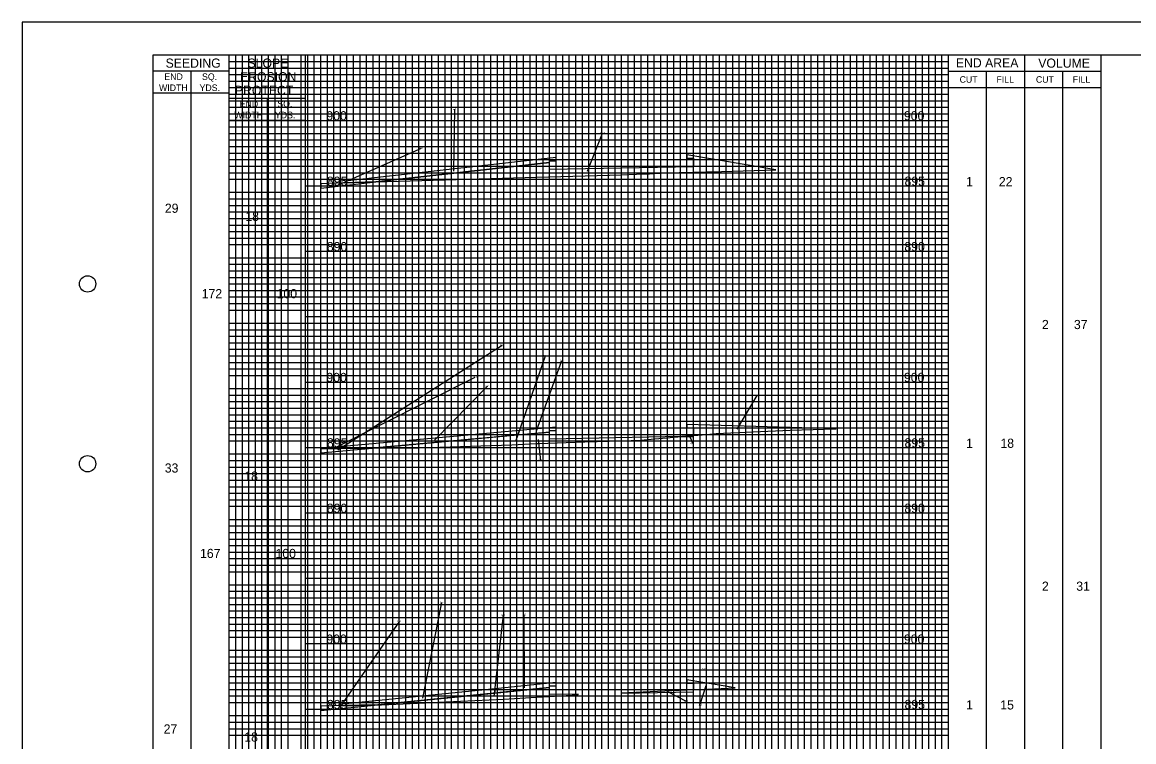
# Model space of a CAD drawing. Extents: x -73 to 160, y -2 to 1877.
# Drawn here: x -10 to 75, y 52.5 to 107.5 of the extents above; entities that cross this region are included whole.
import ezdxf

# ---------------------------------------------------------------- set-up
doc = ezdxf.new("R2010")
doc.units = 0
for name, color, linetype in [('DR_P_Flood_Boundary', 7, 'Continuous'), ('GK_Cells', 7, 'Continuous'), ('RD_X_Fence', 7, 'Continuous'), ('TX_X_5', 7, 'Continuous'), ('UT_P_Water_Cells', 7, 'Continuous'), ('XS_P_Pavt_Surface', 7, 'Continuous'), ('XS_X_Ground_Line', 7, 'Continuous')]:
    doc.layers.add(name, color=color, linetype=linetype)

msp = doc.modelspace()

# ---------------------------------------------------------------- linework, layer by layer
at = {"layer": 'DR_P_Flood_Boundary'}
for p, q in [((15.832, 0), (15.832, 105)), ((20.832, 0), (20.832, 105)), ((25.832, 0), (25.832, 105)), ((30.832, 0), (30.832, 105)), ((35.832, 0), (35.832, 105)), ((40.832, 0), (40.832, 105)), ((45.832, 0), (45.832, 105)), ((50.832, 0), (50.832, 105)), ((55.832, 0), (55.832, 105)), ((5.832, 100), (60.832, 100)), ((11.665, 95), (60.832, 95)), ((11.665, 90), (60.832, 90)), ((11.665, 85), (60.832, 85)), ((11.665, 80), (60.832, 80)), ((11.665, 75), (60.832, 75)), ((11.665, 70), (60.832, 70)), ((11.665, 65), (60.832, 65)), ((11.665, 60), (60.832, 60)), ((11.665, 55), (60.832, 55))]:
    msp.add_line(p, q, dxfattribs=at)
at = {"layer": 'GK_Cells'}
msp.add_lwpolyline([(0, 105), (157.5, 105), (157.5, 0), (0, 0)], close=True, dxfattribs=at)
for centre in [(-5, 87.5), (-5, 73.75)]:
    msp.add_circle(centre, 0.625, dxfattribs=at)
at = {"layer": 'RD_X_Fence'}
for p, q in [((23.016, 96.129), (23.081, 100.856)), ((33.227, 96.12), (34.386, 99.017)), ((14.249, 95.09), (20.533, 97.869)), ((30.832, 97.162), (14.91, 95.382)), ((30.332, 96.902), (30.832, 96.912)), ((30.332, 96.776), (30.332, 96.902)), ((30.832, 97.058), (30.832, 97.162)), ((30.832, 96.912), (30.832, 97.058)), ((47.628, 96.229), (40.832, 97.362)), ((40.832, 97.112), (41.332, 97.122)), ((41.332, 97.122), (41.332, 96.455)), ((30.332, 96.776), (17.034, 95.29)), ((17.034, 95.29), (30.332, 96.776)), ((30.332, 96.235), (30.332, 96.776)), ((41.332, 96.455), (30.332, 96.235)), ((40.235, 96.02), (42.332, 96.069)), ((12.833, 94.82), (17.034, 95.29)), ((14.625, 95.219), (12.833, 95.15)), ((14.91, 95.382), (14.611, 95.25)), ((17.034, 95.29), (14.625, 95.219)), ((14.625, 95.219), (17.034, 95.29)), ((17.034, 95.29), (29.332, 95.65)), ((29.332, 95.65), (35.832, 95.841)), ((38.255, 95.926), (38.86, 95.952)), ((38.86, 95.952), (40.235, 96.02)), ((12.833, 95.15), (12.833, 94.82)), ((14.141, 74.81), (26.701, 82.806)), ((27.741, 75.48), (30.016, 81.999)), ((29.336, 76.257), (31.276, 81.639)), ((13.897, 74.966), (24.643, 80.369)), ((21.519, 75.544), (25.574, 79.685)), ((44.662, 76.391), (46.189, 78.96)), ((30.832, 76.553), (28.027, 76.297)), ((30.832, 76.449), (30.832, 76.553)), ((52.245, 76.425), (40.832, 76.753)), ((40.832, 76.503), (41.332, 76.513)), ((41.332, 76.513), (41.332, 75.909)), ((28.027, 76.297), (14.544, 75.066)), ((30.332, 76.177), (16.757, 74.938)), ((16.757, 74.938), (27.908, 75.956)), ((27.908, 75.956), (28.027, 76.297)), ((28.027, 76.297), (27.908, 75.956)), ((27.908, 75.956), (30.332, 76.177)), ((30.332, 76.293), (30.832, 76.303)), ((30.332, 76.177), (30.332, 76.293)), ((30.332, 75.626), (30.332, 76.177)), ((40.428, 75.828), (30.332, 75.626)), ((30.832, 76.303), (30.832, 76.449)), ((41.327, 75.909), (40.428, 75.828)), ((40.428, 75.828), (41.332, 75.846)), ((41.029, 75.861), (41.277, 75.294)), ((14.544, 75.066), (12.833, 74.91)), ((12.833, 74.58), (16.757, 74.938)), ((16.757, 74.938), (12.833, 74.91)), ((12.833, 74.91), (14.316, 74.921)), ((12.833, 74.91), (12.833, 74.58)), ((14.544, 75.066), (14.316, 74.921)), ((14.316, 74.921), (14.544, 75.066)), ((14.316, 74.921), (16.757, 74.938)), ((29.462, 75.605), (29.62, 74.009)), ((29.492, 75.305), (33.032, 75.416)), ((20.631, 55.846), (22.093, 63.149)), ((26.087, 55.967), (26.81, 62.171)), ((28.415, 56.625), (28.382, 62.213)), ((14.305, 55.148), (18.867, 61.716)), ((30.832, 57.03), (26.156, 56.559)), ((44.508, 56.617), (40.832, 57.23)), ((40.832, 56.98), (41.332, 56.99)), ((41.332, 56.99), (41.332, 56.475)), ((26.156, 56.559), (14.468, 55.384)), ((30.332, 56.649), (16.931, 55.302)), ((16.931, 55.302), (26.117, 56.225)), ((26.117, 56.225), (30.332, 56.649)), ((26.117, 56.225), (26.156, 56.559)), ((26.156, 56.559), (26.117, 56.225)), ((30.332, 56.77), (30.832, 56.78)), ((30.332, 56.649), (30.332, 56.77)), ((30.332, 56.103), (30.332, 56.649)), ((32.519, 56.147), (30.332, 56.103)), ((41.332, 56.475), (35.832, 56.228)), ((35.833, 56.213), (41.332, 56.323)), ((39.337, 56.334), (40.812, 55.57)), ((41.332, 56.475), (44.508, 56.617)), ((41.332, 56.323), (41.332, 56.475)), ((42.276, 56.776), (41.82, 55.342)), ((16.928, 55.329), (12.833, 55.219)), ((12.833, 54.889), (16.931, 55.302)), ((14.468, 55.384), (14.376, 55.25)), ((14.376, 55.25), (16.931, 55.302)), ((29.332, 55.906), (32.52, 56.079)), ((12.833, 55.219), (12.833, 54.889))]:
    msp.add_line(p, q, dxfattribs=at)
for points in [[(40.832, 97.362), (40.832, 97.258), (40.832, 97.112)], [(42.332, 96.069), (43.472, 96.095), (47.628, 96.229)], [(14.611, 95.25), (14.625, 95.219)], [(35.832, 95.841), (36.98, 95.881), (37.971, 95.916), (38.255, 95.926)], [(40.832, 76.753), (40.832, 76.649), (40.832, 76.503)], [(37.293, 75.549), (37.791, 75.593), (40.428, 75.828)], [(41.332, 75.846), (41.327, 75.909)], [(41.332, 75.909), (42.332, 75.998), (43.061, 76.063), (48.714, 76.326), (52.245, 76.425)], [(16.757, 74.938), (20.355, 74.964), (27.435, 75.203), (29.344, 75.3), (29.492, 75.305)], [(33.032, 75.416), (35.832, 75.503), (37.293, 75.549)], [(30.832, 56.78), (30.832, 56.925), (30.832, 57.03)], [(40.832, 57.23), (40.832, 57.125), (40.832, 56.98)], [(32.52, 56.079), (32.519, 56.147)], [(35.832, 56.228), (35.833, 56.213)], [(16.931, 55.302), (16.928, 55.329)], [(16.931, 55.302), (26.792, 55.767), (29.332, 55.906)]]:
    msp.add_lwpolyline(points, dxfattribs=at)
at = {"layer": 'TX_X_5'}
msp.add_lwpolyline([(-10, -2.5), (160, -2.5), (160, 107.5), (-10, 107.5)], close=True, dxfattribs=at)
at = {"layer": 'UT_P_Water_Cells'}
for p, q in [((6.332, 0), (6.332, 105)), ((6.832, 0), (6.832, 105)), ((7.332, 0), (7.332, 105)), ((7.832, 0), (7.832, 105)), ((8.332, 0), (8.332, 105)), ((8.832, 0), (8.832, 105)), ((9.332, 0), (9.332, 105)), ((9.832, 0), (9.832, 105)), ((10.332, 0), (10.332, 105)), ((11.332, 0), (11.332, 105)), ((11.832, 0), (11.832, 105)), ((12.332, 0), (12.332, 105)), ((12.832, 0), (12.832, 105)), ((13.332, 0), (13.332, 105)), ((13.832, 0), (13.832, 105)), ((14.332, 0), (14.332, 105)), ((14.832, 0), (14.832, 105)), ((15.332, 0), (15.332, 105)), ((16.332, 0), (16.332, 105)), ((16.832, 0), (16.832, 105)), ((17.332, 0), (17.332, 105)), ((17.832, 0), (17.832, 105)), ((18.332, 0), (18.332, 105)), ((18.832, 0), (18.832, 105)), ((19.332, 0), (19.332, 105)), ((19.832, 0), (19.832, 105)), ((20.332, 0), (20.332, 105)), ((21.332, 0), (21.332, 105)), ((21.832, 0), (21.832, 105)), ((22.332, 0), (22.332, 105)), ((22.832, 0), (22.832, 105)), ((23.332, 0), (23.332, 105)), ((23.832, 0), (23.832, 105)), ((24.332, 0), (24.332, 105)), ((24.832, 0), (24.832, 105)), ((25.332, 0), (25.332, 105)), ((26.332, 0), (26.332, 105)), ((26.832, 0), (26.832, 105)), ((27.332, 0), (27.332, 105)), ((27.832, 0), (27.832, 105)), ((28.332, 0), (28.332, 105)), ((28.832, 0), (28.832, 105)), ((29.332, 0), (29.332, 105)), ((29.832, 0), (29.832, 105)), ((30.332, 0), (30.332, 105)), ((31.332, 0), (31.332, 105)), ((31.832, 0), (31.832, 105)), ((32.332, 0), (32.332, 105)), ((32.832, 0), (32.832, 105)), ((33.332, 0), (33.332, 105)), ((33.832, 0), (33.832, 105)), ((34.332, 0), (34.332, 105)), ((34.832, 0), (34.832, 105)), ((35.332, 0), (35.332, 105)), ((36.332, 0), (36.332, 105)), ((36.832, 0), (36.832, 105)), ((37.332, 0), (37.332, 105)), ((37.832, 0), (37.832, 105)), ((38.332, 0), (38.332, 105)), ((38.832, 0), (38.832, 105)), ((39.332, 0), (39.332, 105)), ((39.832, 0), (39.832, 105)), ((40.332, 0), (40.332, 105)), ((41.332, 0), (41.332, 105)), ((41.832, 0), (41.832, 105)), ((42.332, 0), (42.332, 105)), ((42.832, 0), (42.832, 105)), ((43.332, 0), (43.332, 105)), ((43.832, 0), (43.832, 105)), ((44.332, 0), (44.332, 105)), ((44.832, 0), (44.832, 105)), ((45.332, 0), (45.332, 105)), ((46.332, 0), (46.332, 105)), ((46.832, 0), (46.832, 105)), ((47.332, 0), (47.332, 105)), ((47.832, 0), (47.832, 105)), ((48.332, 0), (48.332, 105)), ((48.832, 0), (48.832, 105)), ((49.332, 0), (49.332, 105)), ((49.832, 0), (49.832, 105)), ((50.332, 0), (50.332, 105)), ((51.332, 0), (51.332, 105)), ((51.832, 0), (51.832, 105)), ((52.332, 0), (52.332, 105)), ((52.832, 0), (52.832, 105)), ((53.332, 0), (53.332, 105)), ((53.832, 0), (53.832, 105)), ((54.332, 0), (54.332, 105)), ((54.832, 0), (54.832, 105)), ((55.332, 0), (55.332, 105)), ((56.332, 0), (56.332, 105)), ((56.832, 0), (56.832, 105)), ((57.332, 0), (57.332, 105)), ((57.832, 0), (57.832, 105)), ((58.332, 0), (58.332, 105)), ((58.832, 0), (58.832, 105)), ((59.332, 0), (59.332, 105)), ((59.832, 0), (59.832, 105)), ((60.332, 0), (60.332, 105)), ((5.832, 104.5), (60.832, 104.5)), ((5.832, 104), (60.832, 104)), ((5.832, 103.5), (60.832, 103.5)), ((5.832, 103), (60.832, 103)), ((5.832, 102.5), (60.832, 102.5)), ((5.832, 102), (60.832, 102)), ((5.832, 101.5), (60.832, 101.5)), ((5.832, 101), (60.832, 101)), ((5.832, 100.5), (60.832, 100.5)), ((5.832, 99.5), (60.832, 99.5)), ((5.832, 99), (60.832, 99)), ((5.832, 98.5), (60.832, 98.5)), ((5.832, 98), (60.832, 98)), ((5.832, 97.5), (60.832, 97.5)), ((5.832, 97), (60.832, 97)), ((5.832, 96.5), (60.832, 96.5)), ((5.832, 96), (60.832, 96)), ((5.832, 95.5), (60.832, 95.5)), ((5.832, 94.5), (60.832, 94.5)), ((5.832, 94), (60.832, 94)), ((5.832, 93.5), (60.832, 93.5)), ((5.832, 93), (60.832, 93)), ((5.832, 92.5), (60.832, 92.5)), ((5.832, 92), (60.832, 92)), ((5.832, 91.5), (60.832, 91.5)), ((5.832, 91), (60.832, 91)), ((5.832, 90.5), (60.832, 90.5)), ((5.832, 89.5), (60.832, 89.5)), ((5.832, 89), (60.832, 89)), ((5.832, 88.5), (60.832, 88.5)), ((5.832, 88), (60.832, 88)), ((5.832, 87.5), (60.832, 87.5)), ((5.832, 87), (60.832, 87)), ((5.832, 86.5), (60.832, 86.5)), ((5.832, 86), (60.832, 86)), ((5.832, 85.5), (60.832, 85.5)), ((5.832, 84.5), (60.832, 84.5)), ((5.832, 84), (60.832, 84)), ((5.832, 83.5), (60.832, 83.5)), ((5.832, 83), (60.832, 83)), ((5.832, 82.5), (60.832, 82.5)), ((5.832, 82), (60.832, 82)), ((5.832, 81.5), (60.832, 81.5)), ((5.832, 81), (60.832, 81)), ((5.832, 80.5), (60.832, 80.5)), ((5.832, 79.5), (60.832, 79.5)), ((5.832, 79), (60.832, 79)), ((5.832, 78.5), (60.832, 78.5)), ((5.832, 78), (60.832, 78)), ((5.832, 77.5), (60.832, 77.5)), ((5.832, 77), (60.832, 77)), ((5.832, 76.5), (60.832, 76.5)), ((5.832, 76), (60.832, 76)), ((5.832, 75.5), (60.832, 75.5)), ((5.832, 74.5), (60.832, 74.5)), ((5.832, 74), (60.832, 74)), ((5.832, 73.5), (60.832, 73.5)), ((5.832, 73), (60.832, 73)), ((5.832, 72.5), (60.832, 72.5)), ((5.832, 72), (60.832, 72)), ((5.832, 71.5), (60.832, 71.5)), ((5.832, 71), (60.832, 71)), ((5.832, 70.5), (60.832, 70.5)), ((5.832, 69.5), (60.832, 69.5)), ((5.832, 69), (60.832, 69)), ((5.832, 68.5), (60.832, 68.5)), ((5.832, 68), (60.832, 68)), ((5.832, 67.5), (60.832, 67.5)), ((5.832, 67), (60.832, 67)), ((5.832, 66.5), (60.832, 66.5)), ((5.832, 66), (60.832, 66)), ((5.832, 65.5), (60.832, 65.5)), ((5.832, 64.5), (60.832, 64.5)), ((5.832, 64), (60.832, 64)), ((5.832, 63.5), (60.832, 63.5)), ((5.832, 63), (60.832, 63)), ((5.832, 62.5), (60.832, 62.5)), ((5.832, 62), (60.832, 62)), ((5.832, 61.5), (60.832, 61.5)), ((5.832, 61), (60.832, 61)), ((5.832, 60.5), (60.832, 60.5)), ((5.832, 59.5), (60.832, 59.5)), ((5.832, 59), (60.832, 59)), ((5.832, 58.5), (60.832, 58.5)), ((5.832, 58), (60.832, 58)), ((5.832, 57.5), (60.832, 57.5)), ((5.832, 57), (60.832, 57)), ((5.832, 56.5), (60.832, 56.5)), ((5.832, 56), (60.832, 56)), ((5.832, 55.5), (60.832, 55.5)), ((5.832, 54.5), (60.832, 54.5)), ((5.832, 54), (60.832, 54)), ((5.832, 53.5), (60.832, 53.5)), ((5.832, 53), (60.832, 53))]:
    msp.add_line(p, q, dxfattribs=at)
at = {"layer": 'XS_X_Ground_Line'}
for p, q in [((5.832, 0), (5.832, 105)), ((5.832, 0), (5.832, 105)), ((11.665, 0), (11.665, 105)), ((60.832, 0), (60.832, 105)), ((66.667, 0), (66.667, 105)), ((72.5, 0), (72.5, 105)), ((5.832, 103.75), (0, 103.75)), ((2.916, 0), (2.916, 103.75)), ((60.832, 103.75), (72.5, 103.75)), ((63.75, 0), (63.75, 103.75)), ((69.583, 0), (69.583, 103.75)), ((5.832, 102.083), (0, 102.083)), ((60.832, 102.5), (72.5, 102.5)), ((11.665, 101.667), (5.832, 101.667)), ((8.749, 0), (8.749, 101.667)), ((11.665, 100), (5.832, 100))]:
    msp.add_line(p, q, dxfattribs=at)

# ---------------------------------------------------------------- texts
at = {"layer": 'RD_X_Fence'}
for s, p in [('5.0', (22.92, 100.786)), ('16.7', (34.19, 98.947)), ('0.7', (20.363, 97.799)), ('0.6', (26.535, 82.736)), ('8.5', (29.857, 81.929)), ('0.9', (31.111, 81.569)), ('0.1', (24.502, 80.299)), ('4.2', (25.415, 79.615)), ('4.1', (46.053, 78.89)), ('0.0', (41.118, 75.224)), ('7.3', (29.475, 73.939)), ('3.6', (21.932, 63.079)), ('5.0', (26.648, 62.101)), ('1.5', (28.25, 62.143)), ('0.7', (18.698, 61.646)), ('3.7', (41.98, 57.994)), ('0.5', (40.66, 55.5)), ('1.2', (41.702, 55.272))]:
    msp.add_text(s, height=0.14, dxfattribs=at).set_placement(p)
at = {"layer": 'XS_P_Pavt_Surface'}
for s, p in [('900', (13.259, 100)), ('900', (57.427, 100)), ('895', (13.303, 95)), ('895', (57.471, 95)), ('1', (62.173, 94.968)), ('22', (64.684, 94.968)), ('29', (0.907, 92.934)), ('18', (7.063, 92.315)), ('890', (13.292, 90)), ('890', (57.46, 90)), ('172', (3.724, 86.403)), ('100', (9.454, 86.403)), ('2', (67.977, 84.044)), ('37', (70.424, 84.044)), ('900', (13.259, 80)), ('900', (57.427, 80)), ('895', (13.303, 75)), ('895', (57.471, 75)), ('1', (62.173, 74.968)), ('18', (64.803, 74.968)), ('33', (0.899, 73.077)), ('18', (6.98, 72.458)), ('890', (13.292, 70)), ('890', (57.46, 70)), ('167', (3.597, 66.546)), ('100', (9.371, 66.546)), ('2', (67.977, 64.044)), ('31', (70.603, 64.044)), ('900', (13.259, 60)), ('900', (57.427, 60)), ('895', (13.303, 55)), ('895', (57.471, 55)), ('1', (62.173, 54.968)), ('15', (64.792, 54.968)), ('27', (0.814, 53.132)), ('18', (6.98, 52.513))]:
    msp.add_text(s, height=0.7, dxfattribs=at).set_placement(p)
at = {"layer": 'XS_X_Ground_Line'}
for s, height, p in [('SEEDING', 0.7, (0.964, 104.025)), ('SLOPE', 0.7, (7.228, 104.025)), ('END AREA', 0.7, (61.394, 104.047)), ('VOLUME', 0.7, (67.698, 104.025)), ('END', 0.5, (0.87, 103.092)), ('SQ.', 0.5, (3.748, 103.092)), ('EROSION', 0.7, (6.649, 102.983)), ('CUT', 0.5, (61.683, 102.875)), ('FILL', 0.5, (64.502, 102.875)), ('CUT', 0.5, (67.517, 102.875)), ('FILL', 0.5, (70.335, 102.875)), ('WIDTH', 0.5, (0.462, 102.242)), ('YDS.', 0.5, (3.563, 102.242)), ('PROTECT.', 0.7, (6.26, 101.942)), ('END', 0.5, (6.631, 101.008)), ('SQ.', 0.5, (9.51, 101.008)), ('WIDTH', 0.5, (6.224, 100.158)), ('YDS.', 0.5, (9.325, 100.158))]:
    msp.add_text(s, height=height, dxfattribs=at).set_placement(p)

doc.saveas('drawing.dxf')
